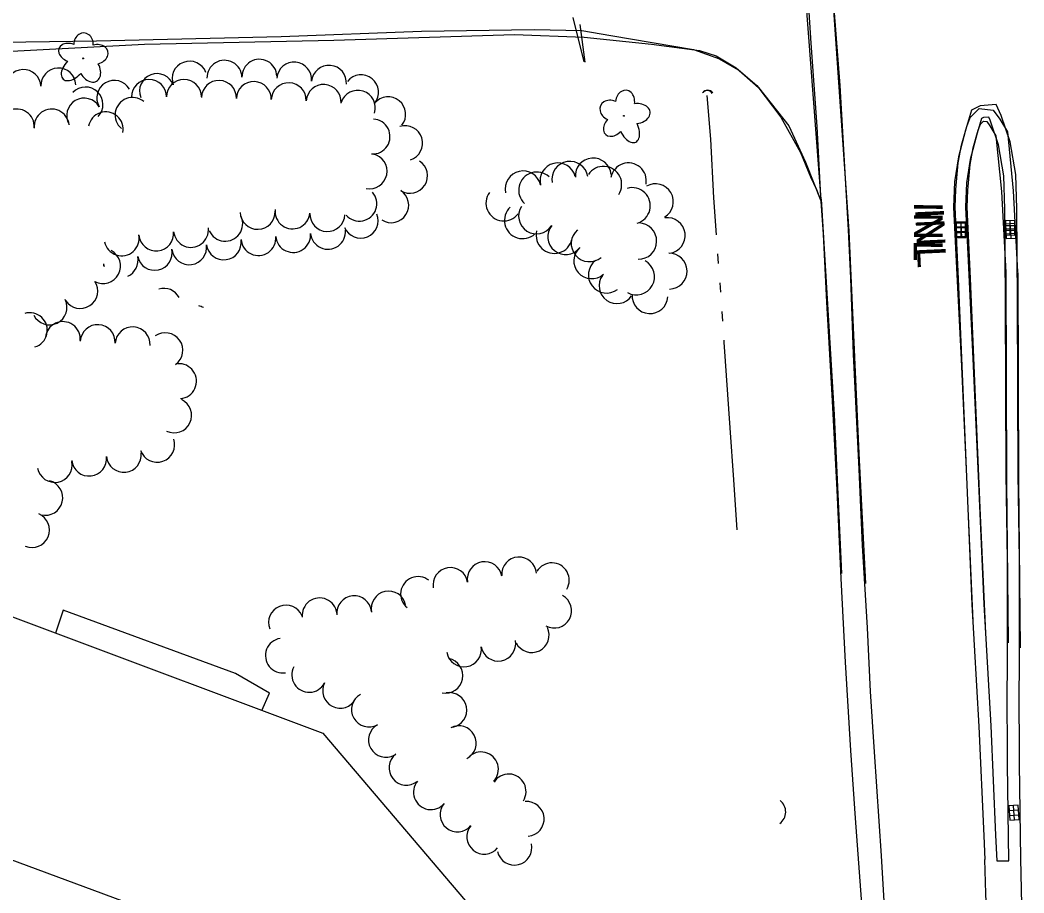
# Model space of a CAD drawing. Extents: x 588843 to 2552415, y 180129 to 269402.
# Drawn here: x 594551.3 to 594760.9, y 184202.7 to 184384.9 of the extents above; entities that cross this region are included whole.
import ezdxf

# ---------------------------------------------------------------- set-up
doc = ezdxf.new("R2010")
doc.units = 0
for name, color, linetype in [('Default', 7, 'Continuous'), ('E_BLD', 7, 'Continuous'), ('E_BLD_HvyDash', 7, 'Continuous'), ('E_DRN', 7, 'Continuous'), ('E_DRN_Text', 7, 'Continuous'), ('E_DWY', 7, 'Continuous'), ('E_FEN_P', 7, 'Continuous'), ('E_LAND_TreeLine_P', 7, 'Continuous'), ('E_LAND_Vegetation', 7, 'Continuous'), ('E_RDWY', 7, 'Continuous'), ('E_RDWY_C_and_G', 7, 'Continuous'), ('E_RDWY_Gravel', 7, 'Continuous'), ('E_WAL', 7, 'Continuous'), ('E_WTR_P', 7, 'Continuous')]:
    doc.layers.add(name, color=color, linetype=linetype)

# ---------------------------------------------------------------- blocks, each defined once
blk = doc.blocks.new('CULV2')
at = {"layer": 'E_DRN'}
blk.add_arc((19.7, 14.8), 24.6, 216.8699, 323.1301, dxfattribs=at)
blk = doc.blocks.new('DTRE')
at = {"layer": 'Default'}
blk.add_circle((-0.18, 0), 0.183, dxfattribs=at)
for centre, major_axis, ratio in [((-1.87, 5.32), (1.36, -4.98), 0.782863), ((-5.87, 0.15), (4.93, -0.12), 0.832022), ((4.06, 2.74), (-5.27, -2.93), 0.691916), ((-2.49, -5.24), (1.8, 4.86), 0.716896), ((3.54, -3.71), (-5.01, 4.58), 0.560249)]:
    blk.add_ellipse(centre, major_axis=major_axis, ratio=ratio, start_param=1.570796, end_param=4.712389, dxfattribs=at)
blk = doc.blocks.new('INLO')
at = {"layer": 'E_DRN'}
for p, q in [((2, -4), (2, 0)), ((4, -4), (4, 0)), ((6, -2), (0, -2))]:
    blk.add_line(p, q, dxfattribs=at)
blk.add_lwpolyline([(0, -4), (6, -4), (6, 0), (0, 0), (0, -4)], close=True, dxfattribs=at)
blk = doc.blocks.new('INLT_57')
at = {"layer": 'E_DRN_Text'}
blk.add_text('INL', height=12, dxfattribs=at).set_placement((-11.03, -6))
blk = doc.blocks.new('CULV2_4')
at = {"layer": 'E_DRN'}
blk.add_arc((65, 48), 80.7, 216.8699, 323.1301, dxfattribs=at)
blk = doc.blocks.new('INLO_3')
at = {"layer": 'E_DRN'}
for p, q in [((6.6, -13.1), (6.6, 0)), ((13.1, -13.1), (13.1, 0)), ((19.7, -6.6), (0, -6.6))]:
    blk.add_line(p, q, dxfattribs=at)
blk.add_lwpolyline([(0, -13.1), (19.7, -13.1), (19.7, 0), (0, 0)], close=True, dxfattribs=at)
blk = doc.blocks.new('INLT_35_1')
at = {"layer": 'E_DRN_Text'}
blk.add_text('INL', height=39.37, dxfattribs=at).set_placement((-36.2, -19.7))
blk = doc.blocks.new('DTRE_4')
at = {"layer": 'E_LAND_Vegetation'}
blk.add_circle((-0.6, 0), 0.601, dxfattribs=at)
for centre, major_axis, ratio in [((-6.1, 17.5), (4.5, -16.3), 0.782863), ((-19.3, 0.5), (16.2, -0.4), 0.832022), ((13.3, 9), (-17.3, -9.6), 0.691916), ((-8.2, -17.2), (5.9, 15.9), 0.716896), ((11.6, -12.2), (-16.4, 15), 0.560249)]:
    blk.add_ellipse(centre, major_axis=major_axis, ratio=ratio, start_param=1.570796, end_param=4.712389, dxfattribs=at)

msp = doc.modelspace()

# ---------------------------------------------------------------- linework, layer by layer
at = {"layer": 'E_BLD'}
msp.add_lwpolyline([(594420.1, 184278.97), (594499.27, 184279.14), (594614.5, 184236), (594658.94, 184183.75), (594623.49, 184153.78), (594588.64, 184195.04), (594495.27, 184229.58), (594420.94, 184229.53)], dxfattribs=at)
at = {"layer": 'E_BLD_HvyDash'}
msp.add_lwpolyline([(594601.78, 184240.76), (594603.37, 184244.37), (594596.24, 184248.49), (594560.24, 184261.69), (594558.67, 184256.91)], dxfattribs=at)
at = {"layer": 'E_DWY'}
for points in [[(594468.85, 184389.01), (594479.38, 184384.76), (594491.77, 184382.6), (594504.13, 184380.72), (594516.73, 184380.2), (594542.61, 184380.24), (594567.26, 184380.58), (594605.77, 184381.49), (594635.12, 184382.57), (594658.62, 184382.91), (594668.59, 184382.71), (594674.6, 184381.67), (594691.89, 184378.75), (594697.3, 184376.81), (594701.27, 184374.53), (594705.15, 184371.22), (594710.13, 184364.63), (594714.27, 184357.25), (594716.31, 184352.18), (594717.59, 184349.5), (594718.6, 184346.81)], [(594471.01, 184386.2), (594477.79, 184383.03), (594484.6, 184381.08), (594494.69, 184379.12), (594512.17, 184377.6), (594541.47, 184378.02), (594577.22, 184379.87), (594616.79, 184380.73), (594654.5, 184381.92), (594669.08, 184381.33), (594683.1, 184379.88), (594693.16, 184378.53), (594696.63, 184377.44), (594700.82, 184374.91), (594705.49, 184370.81), (594711.81, 184362.85), (594715.26, 184355.21), (594718.62, 184346.79)]]:
    msp.add_lwpolyline(points, dxfattribs=at)
at = {"layer": 'E_FEN_P'}
msp.add_lwpolyline([(594668.18, 184383.97), (594669.2, 184376.12)], dxfattribs=at)
at = {"layer": 'E_LAND_TreeLine_P'}
for centre, radius, start, end in [((594559.26, 184371.24), 3.65, 2.4652, 182.4652), ((594586.67, 184372.66), 3.65, 20.9001, 200.9001), ((594593.95, 184372.86), 3.65, 1.5182, 181.5182), ((594601.24, 184373.06), 3.65, 1.5182, 181.5182), ((594608.51, 184372.47), 3.65, 354.8705, 174.8705), ((594615.77, 184371.81), 3.65, 354.8705, 174.8705), ((594551.97, 184370.93), 3.65, 2.4652, 182.4652), ((594579.86, 184370.06), 3.65, 20.9001, 200.9001), ((594622.48, 184369.81), 3.65, 321.0664, 141.0664), ((594564.92, 184367.26), 3.65, 316.133, 136.133), ((594570.94, 184368.65), 3.65, 30.4425, 210.4425), ((594578.19, 184368.83), 3.65, 0.1213, 180.1213), ((594585.49, 184368.85), 3.65, 0.1213, 180.1213), ((594592.79, 184368.64), 3.65, 358.1104, 178.1104), ((594600.08, 184368.4), 3.65, 358.1104, 178.1104), ((594607.37, 184368.16), 3.65, 358.1104, 178.1104), ((594614.66, 184367.8), 3.65, 356.1738, 176.1738), ((594564.65, 184364.95), 3.65, 30.4425, 210.4425), ((594574.75, 184365.08), 3.65, 50.4008, 230.4008), ((594621.8, 184366.58), 3.65, 342.4708, 162.4708), ((594628.15, 184365.23), 3.65, 321.0664, 141.0664), ((594550.59, 184362.68), 3.65, 355.7817, 175.7817), ((594557.86, 184362.67), 3.65, 5.3264, 185.3264), ((594569.16, 184362.08), 3.65, 349.2247, 169.2247), ((594624.87, 184360.58), 3.65, 267.0492, 87.0492), ((594631.68, 184359.19), 3.65, 287.4187, 107.4187), ((594624.25, 184353.33), 3.65, 258.4608, 78.4608), ((594670.95, 184352.36), 3.73, 4.5335, 184.5335), ((594632.7, 184352.39), 3.65, 237.4429, 57.4429), ((594663.58, 184351.34), 3.73, 13.6215, 193.6215), ((594666.11, 184351.61), 3.79, 9.1138, 189.1138), ((594673.11, 184350.57), 3.79, 326.4767, 146.4767), ((594678.32, 184351.35), 3.73, 348.9898, 168.9898), ((594656.31, 184349.66), 3.73, 12.5538, 192.5538), ((594659.18, 184349.38), 3.79, 47.4652, 227.4652), ((594679.08, 184346.12), 3.79, 286.0356, 106.0356), ((594683.96, 184346.98), 3.73, 300.3428, 120.3428), ((594622.12, 184346.57), 3.65, 221.0284, 41.0284), ((594628.78, 184346.24), 3.65, 237.4429, 57.4429), ((594652.28, 184346.69), 3.73, 143.4962, 323.4962), ((594656.21, 184343.05), 3.79, 132.7665, 312.7665), ((594659.11, 184343.98), 3.73, 147.3123, 327.3123), ((594594.11, 184342.38), 3.65, 204.39, 24.39), ((594600.88, 184344.86), 3.65, 181.7142, 1.7142), ((594608.17, 184344.95), 3.65, 174.2035, 354.2035), ((594615.45, 184344.4), 3.65, 177.7177, 357.7177), ((594622.41, 184343.01), 3.65, 202.3977, 22.3977), ((594686.43, 184339.91), 3.73, 277.515, 97.515), ((594586.96, 184341.09), 3.65, 186.1991, 6.1991), ((594665.19, 184339.67), 3.73, 141.0218, 321.0218), ((594680.41, 184338.74), 3.79, 269.1313, 89.1313), ((594572.49, 184339.32), 3.65, 191.539, 11.539), ((594579.7, 184340.35), 3.65, 185.53, 5.53), ((594601.04, 184339.38), 3.65, 185.1549, 5.1549), ((594608.3, 184340.03), 3.65, 185.1549, 5.1549), ((594615.56, 184340.69), 3.65, 185.1549, 5.1549), ((594662.82, 184339.97), 3.79, 166.3835, 346.3835), ((594670.15, 184338.24), 3.79, 130.3402, 310.3402), ((594579.39, 184336.31), 3.65, 192.28, 12.28), ((594586.58, 184337.47), 3.65, 187.9927, 7.9927), ((594593.8, 184338.49), 3.65, 187.9927, 7.9927), ((594670.64, 184334.63), 3.73, 131.3108, 311.3108), ((594568.58, 184333.53), 3.65, 242.0823, 62.0823), ((594572.26, 184334.76), 3.65, 294.0526, 12.28), ((594686.81, 184332.47), 3.73, 271.196, 91.196), ((594572.26, 184334.76), 3.65, 192.28, 200.719), ((594565.13, 184333.27), 3.65, 3.7283, 10.0336), ((594673.73, 184331.69), 3.79, 127.1603, 307.1603), ((594679.96, 184331.3), 3.79, 241.0356, 61.0356), ((594675.92, 184329.43), 3.73, 144.9178, 324.9178), ((594563.84, 184328.34), 3.65, 212.9251, 32.9251), ((594581.28, 184325.24), 3.65, 28.0432, 106.7284), ((594557.4, 184324.91), 3.65, 206.2973, 26.2973), ((594682.81, 184327.34), 3.73, 176.0284, 356.0284), ((594587.67, 184321.73), 3.65, 59.0765, 75.6951), ((594553.3, 184320.14), 3.65, 287.1158, 107.1158), ((594560.2, 184318.29), 3.65, 354.9145, 174.9145), ((594567.47, 184317.65), 3.65, 356.415, 176.415), ((594574.76, 184317.19), 3.65, 356.415, 176.415), ((594581.61, 184315.96), 3.65, 305.3183, 125.3183), ((594584.45, 184309.5), 3.65, 275.0789, 95.0789), ((594583.43, 184302.37), 3.65, 244.678, 64.678), ((594579.9, 184296.23), 3.65, 198.9704, 18.9704), ((594565.68, 184293.34), 3.65, 186.294, 6.294), ((594572.93, 184294.14), 3.65, 186.294, 6.294), ((594558.51, 184292.02), 3.65, 190.8056, 10.8056), ((594556.54, 184285.16), 3.65, 256.0278, 76.0278), ((594553.76, 184278.41), 3.65, 247.3522, 67.3522), ((594655.47, 184269.15), 3.63, 3.6529, 183.6529), ((594641.14, 184266.95), 3.63, 9.7207, 189.7207), ((594648.29, 184268.17), 3.63, 9.7207, 189.7207), ((594662.31, 184267.94), 3.63, 329.1995, 149.1995), ((594634.37, 184265.07), 3.63, 51.847, 231.847), ((594613.81, 184260.62), 3.63, 6.4549, 186.4549), ((594621.05, 184261.06), 3.63, 5.7032, 185.7032), ((594628.23, 184262.03), 3.63, 12.1421, 192.1421), ((594662.8, 184261.58), 3.63, 241.4298, 61.4298), ((594606.78, 184259.11), 3.63, 21.8346, 201.8346), ((594658.12, 184256.48), 3.63, 206.0093, 26.0093), ((594606.14, 184252.21), 3.63, 98.8564, 278.8564), ((594651.13, 184254.69), 3.63, 190.5927, 10.5927), ((594643.98, 184253.48), 3.63, 189.262, 9.262), ((594640.11, 184248.01), 3.63, 258.8337, 78.8337), ((594611.64, 184248.17), 3.63, 152.264, 332.264), ((594618.09, 184244.85), 3.63, 152.8003, 332.8003), ((594624.11, 184240.93), 3.63, 119.18, 299.18), ((594640.93, 184240.84), 3.63, 280.6078, 100.6078), ((594627.65, 184234.6), 3.63, 119.18, 299.18), ((594642.88, 184233.92), 3.63, 297.601, 117.601), ((594631.96, 184228.78), 3.63, 128.2323, 308.2323), ((594647.53, 184228.46), 3.63, 316.4479, 136.4479), ((594637.06, 184223.67), 3.63, 139.9814, 319.9814), ((594653.3, 184223.84), 3.63, 327.4754, 147.4754), ((594657.08, 184218.1), 3.63, 274.957, 94.957), ((594642.62, 184219.02), 3.63, 140.2115, 320.2115), ((594648.2, 184214.37), 3.63, 140.2115, 320.2115), ((594654.5, 184212.1), 3.63, 193.2582, 13.2582)]:
    msp.add_arc(centre, radius, start, end, dxfattribs=at)
at = {"layer": 'E_RDWY'}
for points in [[(594710.96, 184459.76), (594716.14, 184459.19), (594724.35, 184340.84), (594726.41, 184294.37), (594727.8, 184267.26)], [(594739.21, 184085.43), (594738.2, 184102.3), (594736.89, 184122.49), (594735.67, 184141.79), (594734.36, 184160.83), (594733.47, 184174.41), (594732.22, 184192.67), (594731.13, 184210.37), (594729.69, 184232.13), (594728.88, 184244.69), (594728.2, 184258.03), (594727.19, 184275.19), (594726.5, 184291.1), (594725.31, 184315.13), (594724.72, 184331.01), (594724.24, 184341.12), (594723.62, 184351.82), (594722.52, 184371.23), (594720.87, 184392.75), (594720.08, 184401.84), (594718.64, 184421.55), (594717.31, 184440.3), (594716.19, 184459.27)], [(594756.93, 184087.04), (594755.96, 184115.3), (594755.24, 184139.28), (594754.49, 184162.03), (594753.73, 184183.16), (594752.95, 184202.54), (594752.73, 184209.62)], [(594760.83, 184086.85), (594760.9, 184108.95), (594760.77, 184128.36), (594760.74, 184149.12), (594760.67, 184171.59), (594760.67, 184190.71), (594760.25, 184209.79)]]:
    msp.add_lwpolyline(points, dxfattribs=at)
at = {"layer": 'E_RDWY_C_and_G'}
for points in [[(594760.25, 184209.79), (594759.94, 184229.57), (594759.93, 184246.22), (594759.95, 184247.7), (594759.95, 184272.17), (594759.7, 184290.15), (594759.65, 184308.06), (594759.53, 184326.37), (594759.42, 184345.48), (594759.18, 184352.65), (594758.02, 184359.49), (594756.17, 184364.94), (594755.08, 184367.3), (594751.78, 184366.98), (594749.93, 184366.1), (594748.71, 184361.94), (594747.2, 184356.31), (594746.39, 184351.12), (594746.19, 184345.85), (594746.76, 184334.51), (594747.76, 184314.06), (594748.88, 184289.63), (594750.03, 184262.84), (594751.46, 184237.4), (594752.49, 184214.58), (594752.73, 184209.62)], [(594749.24, 184282.93), (594747.24, 184330.86), (594746.56, 184345.82), (594746.66, 184349.52), (594747.18, 184355.08), (594747.88, 184358.79), (594749, 184362.71), (594749.7, 184364.57), (594751.58, 184366.41), (594754.49, 184366.07), (594755.89, 184364.23), (594757.49, 184361.56), (594758.68, 184349.27), (594759.58, 184332.33)], [(594751.73, 184283.04), (594749.74, 184330.97), (594749.07, 184345.84), (594749.16, 184349.37), (594749.66, 184354.73), (594750.31, 184358.22), (594751.37, 184361.93), (594751.84, 184363.17), (594752.48, 184363.79), (594753.15, 184363.71), (594753.81, 184362.83), (594755.05, 184360.76), (594756.18, 184349.08), (594757.09, 184332.19)], [(594757.09, 184332.19), (594757.29, 184288.44), (594757.59, 184254.86)], [(594759.59, 184332.21), (594759.79, 184288.46), (594760.1, 184253.81)], [(594750.38, 184257.86), (594749.24, 184282.92)], [(594752.93, 184256.8), (594751.73, 184283.04)]]:
    msp.add_lwpolyline(points, dxfattribs=at)
msp.add_lwpolyline([(594757.45, 184247.7), (594757.45, 184272.15), (594757.2, 184290.13), (594757.15, 184308.05), (594757.03, 184326.36), (594756.92, 184345.43), (594756.69, 184352.4), (594755.59, 184358.87), (594753.85, 184364.01), (594753.56, 184364.64), (594752.46, 184364.53), (594752.02, 184364.32), (594751.11, 184361.26), (594749.65, 184355.79), (594748.88, 184350.88), (594748.69, 184345.86), (594749.26, 184334.63), (594750.26, 184314.18), (594751.37, 184289.74), (594752.53, 184262.96), (594753.96, 184237.53), (594754.99, 184214.7), (594755.25, 184209.37), (594757.76, 184209.33), (594757.44, 184229.55), (594757.43, 184246.21), (594757.45, 184247.7)], close=True, dxfattribs=at)
at = {"layer": 'E_RDWY_Gravel'}
for points in [[(594718.58, 184347.5), (594715.37, 184389.59), (594712.84, 184438.02), (594710.96, 184459.76)], [(594735.55, 184085.39), (594734.31, 184102.76), (594733.06, 184120.26), (594731.84, 184137.28), (594730.3, 184156.92), (594728.89, 184176.48), (594726.96, 184201.32), (594725.69, 184218.24), (594724.78, 184232.39), (594723.63, 184250.83), (594722.73, 184268.28), (594721.92, 184286.82), (594720.87, 184306.62), (594719.75, 184325.97), (594719.07, 184340.18), (594718.51, 184348.04), (594717.72, 184362.67), (594716.48, 184380.09), (594715.64, 184393.07), (594714.69, 184408.68), (594713.51, 184422.39), (594712.41, 184438.43), (594711.42, 184449.03), (594711.26, 184450.7)], [(594718.58, 184347.5), (594721.27, 184302.5), (594722.81, 184269.34)]]:
    msp.add_lwpolyline(points, dxfattribs=at)
at = {"layer": 'E_WAL'}
msp.add_lwpolyline([(594669.05, 184376.17), (594666.8, 184385.44)], dxfattribs=at)
at = {"layer": 'E_WTR_P'}
for points in [[(594694.69, 184369.18), (594695.45, 184360.05), (594696.09, 184347.79), (594696.65, 184340.09)], [(594696.94, 184336.08), (594697.08, 184334.07)], [(594697.37, 184330.06), (594697.52, 184328.06)], [(594697.8, 184324.04), (594697.95, 184322.04)], [(594698.23, 184318.03), (594698.26, 184317.63), (594699.5, 184299.76), (594700.24, 184288.93)], [(594700.24, 184288.93), (594700.75, 184281.59), (594700.92, 184278.46)]]:
    msp.add_lwpolyline(points, dxfattribs=at)

# ---------------------------------------------------------------- block references
at = {"layer": 'E_DRN'}
for name, p, xscale, yscale, rotation in [('CULV2', (594695.94, 184369.71), 0.05441949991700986, 0.05441949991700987, -179.77095280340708), ('CULV2_4', (594695.82, 184369.57), 0.014662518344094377, 0.014662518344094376, 173.00284786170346), ('INLO', (594746.7, 184339.69), 0.5, 0.5000000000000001, 90.22904716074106), ('INLO_3', (594746.85, 184339.43), 0.15240030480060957, 0.15240030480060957, 92.5895018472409), ('INLO', (594759.03, 184343), 0.5, 0.5, -90.78493154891), ('INLO_3', (594759.05, 184342.39), 0.15240030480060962, 0.1524003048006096, -86.94113944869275), ('CULV2', (594709.9, 184217.13), 0.12198069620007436, 0.12198069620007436, 88.86511964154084), ('INLO', (594759.72, 184220.97), 0.49999999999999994, 0.5, -86.19461843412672)]:
    msp.add_blockref(name, p, dxfattribs=dict(at, xscale=xscale, yscale=yscale, rotation=rotation))
at = {"layer": 'E_DRN_Text'}
for name, p, xscale, yscale, rotation in [('INLT_57', (594740.92, 184341.47), 0.5000000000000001, 0.5, -90.36283032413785), ('INLT_35_1', (594741.42, 184340.13), 0.15240030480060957, 0.15240030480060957, -87.41049815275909)]:
    msp.add_blockref(name, p, dxfattribs=dict(at, xscale=xscale, yscale=yscale, rotation=rotation))
at = {"layer": 'E_LAND_Vegetation'}
for name, p, xscale, yscale, rotation in [('DTRE', (594564.42, 184376.81), 0.5000000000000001, 0.5, -90.36283032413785), ('DTRE_4', (594677.45, 184364.86), 0.1524003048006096, 0.15240030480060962, -22.11088937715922)]:
    msp.add_blockref(name, p, dxfattribs=dict(at, xscale=xscale, yscale=yscale, rotation=rotation))

doc.saveas('drawing.dxf')
